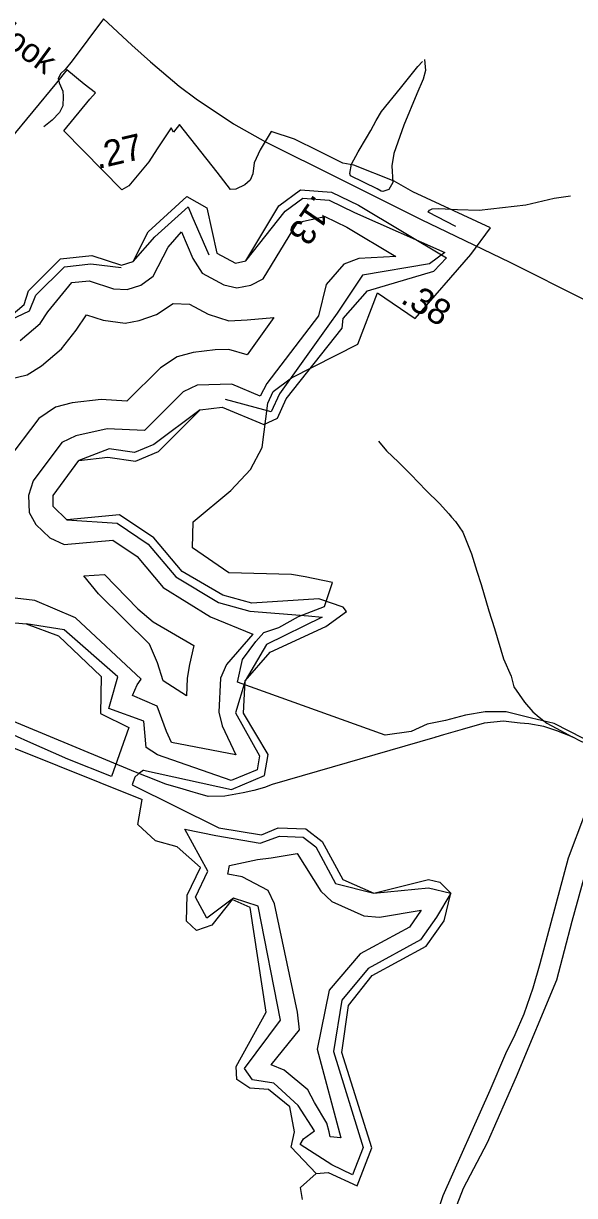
# Model space of a CAD drawing. Extents: x 945666 to 965748, y 644452 to 663300.
# Drawn here: x 953003 to 953350, y 658594 to 659330 of the extents above; entities that cross this region are included whole.
import ezdxf

# ---------------------------------------------------------------- set-up
doc = ezdxf.new("R2010")
doc.units = 0
for name, color, linetype in [('Exist Boundary Political City Limit New', 7, 'Continuous'), ('Exist Hydrographic Buffer Line', 7, 'Continuous'), ('Exist Hydrographic Creek Single Shore', 7, 'Continuous'), ('Exist Hydrographic Lake Shore', 7, 'Continuous'), ('Exist Hydrographic Pond Under 1500 Sq Ft', 7, 'Continuous'), ('Exist Railroad Siding', 7, 'Continuous'), ('Exist Road Primary NC Attributed', 7, 'Continuous'), ('Exist Road Primary US UnDivided 4 Lane Attributed', 7, 'Continuous'), ('Exist Road Secondary Mileage Tenths English Label', 7, 'Continuous'), ('Exist Road Secondary Type 51 Attributed', 7, 'Continuous'), ('Exist Road Secondary Type 51 Label', 7, 'Continuous'), ('Old_Level_49', 7, 'Continuous'), ('Sheet Sticker Preliminary CELL', 7, 'Continuous')]:
    doc.layers.add(name, color=color, linetype=linetype)

msp = doc.modelspace()

# ---------------------------------------------------------------- linework, layer by layer
at = {"layer": 'Exist Boundary Political City Limit New'}
for points in [[(953391.97, 658862.05), (953336.71, 658890.38), (953322.36, 658893.75), (953306.48, 658897.68), (953293.45, 658897.58), (953280.94, 658895.62), (953268.5, 658892.15), (953256.83, 658890), (953246.89, 658885.28), (953230.63, 658882.93), (953137.81, 658916.3), (953140.96, 658930.48), (953149.35, 658941.85), (953154.39, 658947.41), (953163.86, 658950.52), (953176.09, 658957.57), (953192.43, 658963.75), (953197.45, 658978.78), (953180.29, 658982.42), (953171.79, 658983.77), (953132.34, 658984.79), (953109.47, 659000.53), (953109.92, 659016.99), (953133.54, 659036.66), (953146, 659049.73), (953153.2, 659063.49), (953156.84, 659091.4), (953160.28, 659098.69), (953171.75, 659107.3), (953213.43, 659128.48), (953225.74, 659160.62), (953249.3, 659144.59), (953284.37, 659184.62), (953296.8, 659201.46), (953247.94, 659224.06), (953236.3, 659230.59), (953210.83, 659240.69), (953204.06, 659242.04), (953188.82, 659249.51), (953173.59, 659256.98), (953158.89, 659261.89), (953151.99, 659250.3), (953148.25, 659242.25), (953147.44, 659235.3), (953145.72, 659231.39), (953142.33, 659228.42), (953136.72, 659225.72), (953133.43, 659225.4), (953125.03, 659236.39), (953101.47, 659266.3), (953097.55, 659261.43), (953096.22, 659264.26), (953087.41, 659250.94), (953082.01, 659242.77), (953069.65, 659227.85), (953065.06, 659225.24), (953028.79, 659262.3), (953045.11, 659282.14), (953048.53, 659286.17), (953041.52, 659291.64), (953030.66, 659300.52), (953024.08, 659292.44), (952994.44, 659256.47)], [(953272.81, 658580.93), (953279.76, 658598.69), (953294.77, 658627.39), (953312.94, 658668.7), (953338.33, 658729.54), (953347.95, 658766.22), (953358.52, 658804.17)]]:
    msp.add_lwpolyline(points, dxfattribs=at)
at = {"layer": 'Exist Hydrographic Buffer Line'}
for p, q in [((953199.34, 658790.02), (953223.42, 658783.94)), ((953150.86, 658775.64), (953135.24, 658780.64))]:
    msp.add_line(p, q, dxfattribs=at)
for points in [[(953143.13, 659180.63), (953167.68, 659211.76), (953178.8, 659220.01), (953195.38, 659218.69), (953211.29, 659211), (953268.08, 659185.82), (953258.33, 659178.88), (953216.4, 659171.73), (953200.31, 659147.82), (953195.53, 659141.12), (953164.28, 659097.26), (953159.02, 659085.94), (953154.37, 659087.19), (953130.26, 659093.64)], [(953072.3, 659180.25), (953085.82, 659195.7), (953106.78, 659214.63), (953109.2, 659209.02), (953119.81, 659184.39)], [(953001.27, 659130.67), (953013.94, 659141.36), (953018.77, 659148.61), (953033.79, 659167.08), (953044.61, 659168.23), (953059.95, 659163.1), (953068.56, 659162.72), (953077.04, 659165.4), (953084.84, 659171), (953094.24, 659189.31), (953102.67, 659198.8), (953109.66, 659182.14), (953115.63, 659172.98), (953129.13, 659165.54), (953137.48, 659163.72), (953146.25, 659165.35), (953153.89, 659169.34), (953175.55, 659204.65), (953192.61, 659208.49), (953206.37, 659201.84), (953237.33, 659183.43)], [(953214.08, 659182.24), (953204.64, 659178.66), (953193.48, 659165.82), (953188.73, 659146.15), (953156.14, 659103.73), (953152.05, 659095.81), (953134.26, 659103.23), (953112.48, 659102.56), (953103.69, 659098.38), (953079.36, 659074.23), (953055.99, 659075.18), (953036.36, 659070.93), (953027.38, 659066.73), (953009.45, 659042.61), (953006.45, 659033.46), (953006.86, 659022.78), (953011.24, 659015.17), (953019.9, 659006.9), (953028.93, 659002.68), (953059.56, 659005.29), (953074.74, 658995.11), (953091.06, 658975.65), (953120.76, 658957.36), (953147.5, 658946.41)], [(953237.33, 659183.43), (953214.08, 659182.24)], [(952990.73, 659141.56), (953007.24, 659149.31), (953011.18, 659159.17), (953029.05, 659177.02), (953045.75, 659178.8), (953064.71, 659176.5)], [(952993.5, 659106.29), (953005.78, 659109.25), (953014.68, 659114.79), (953027.35, 659125.48), (953036.47, 659137.09), (953042.98, 659146.86), (953053.36, 659143.39), (953067.17, 659141.58), (953075.97, 659143.23), (953086.86, 659146.91), (953097.39, 659153.9), (953107.66, 659153.48), (953119.28, 659147.24), (953132.45, 659143.12), (953143.79, 659143.64), (953160.64, 659145.18), (953143.9, 659121.73), (953132.32, 659124.99), (953123.7, 659124.92), (953109.88, 659123.17), (953099.89, 659120.42), (953089.36, 659113.44), (953068.3, 659092.53), (953052.27, 659093.67), (953034, 659091.58), (953023.57, 659088.77), (953013.04, 659081.79), (952992.66, 659054.87)], [(953114.44, 659087.09), (953085.25, 659065.43), (953073.05, 659060.31), (953057.16, 659062.67), (953038.13, 659055.44)], [(953030.67, 659018.17), (953062.26, 659015.99), (953081.76, 659002.92), (953099.03, 658982.33), (953125.97, 658966.35), (953145.47, 658960.93), (953182.39, 658957.88), (953190.97, 658957.17), (953156.08, 658939.84), (953142.55, 658917.09), (953136.45, 658897.05), (953151.63, 658869.95), (953150.16, 658861.35), (953133.84, 658854.49), (953087.63, 658870.62), (953080.38, 658875.35), (953079.07, 658891.82), (953056.92, 658899.84), (953058.14, 658904.17), (953062.54, 658919.71), (953028.95, 658949.13), (953005.08, 658952.9)], [(953105.72, 658907.64), (953091.08, 658917.05), (953087.5, 658928.48), (953082.45, 658940.06), (953050.42, 658971.73), (953041.21, 658983.01), (953054.16, 658983.89), (953075.14, 658962.3), (953084.76, 658954.2), (953110.33, 658939.38), (953107.66, 658927.37), (953106.21, 658918.71), (953105.72, 658907.64)], [(953147.5, 658946.41), (953130.79, 658927.34), (953127.05, 658918.84), (953126.07, 658897.51), (953128.26, 658888.82), (953136.85, 658870.75), (953096.38, 658878.51), (953093.21, 658885.26), (953087.29, 658901.18), (953071.82, 658907.84), (953074.72, 658914.53), (953077.32, 658918.06), (953036.11, 658956.66), (953010.51, 658967.51), (952994.61, 658969.37)], [(953104.72, 658824.04), (953124.24, 658820.08), (953152.01, 658815.32), (953164.24, 658819.59), (953178.96, 658819.1), (953187.03, 658812.89), (953199.34, 658790.02)], [(953135.24, 658780.64), (953118.56, 658768.18), (953111.41, 658781.39), (953119.17, 658797.73), (953104.72, 658824.04)], [(953253.22, 658773.1), (953245.73, 658762.52), (953214.9, 658745.77), (953195.29, 658723.08), (953187.88, 658685.98), (953202.7, 658630.32), (953195.97, 658630.86), (953195.29, 658634.08), (953193.88, 658639.54), (953186.06, 658652.5), (953182.01, 658660.47), (953167.07, 658672.73), (953159, 658676.11), (953176.64, 658698.14), (953175.57, 658709.12), (953161.13, 658777.2), (953157, 658785.61), (953140.66, 658794.08), (953131.82, 658795.78), (953132.76, 658801.2), (953150.29, 658805.07), (953158.92, 658806.08), (953175.27, 658808.83), (953190.19, 658785.09), (953196.98, 658778.52), (953217.18, 658769.66), (953227.09, 658768.79), (953253.22, 658773.1)], [(953223.42, 658783.94), (953257.86, 658787.1), (953271.77, 658783.87), (953262.87, 658768.74), (953252.81, 658754.54), (953219.86, 658736.64), (953203.42, 658716.62), (953198.18, 658684.53), (953216.74, 658624.26), (953210.08, 658607.17), (953197.01, 658613.34), (953177.09, 658626.06), (953179.28, 658629.73), (953186.23, 658634.73), (953175.84, 658650.65), (953160.53, 658664.65), (953147.26, 658666.62), (953142.23, 658673.88), (953164.8, 658704.11), (953150.86, 658775.64)]]:
    msp.add_lwpolyline(points, dxfattribs=at)
at = {"layer": 'Exist Hydrographic Creek Single Shore'}
msp.add_lwpolyline([(953178.6, 658591.53), (953177.37, 658599.15), (953187.31, 658607.95)], dxfattribs=at)
at = {"layer": 'Exist Hydrographic Lake Shore'}
msp.add_line((953213.76, 659215.58), (953269.15, 659182.65), dxfattribs=at)
for points in [[(952991.22, 659142.59), (953003.89, 659153.28), (953006.61, 659161.94), (953026.67, 659181.99), (953046.32, 659184.09), (953064.9, 659177.88), (953072.3, 659180.25), (953081.61, 659198.9), (953106.05, 659220.97), (953118.53, 659214.05), (953124.88, 659185.52), (953136.51, 659179.27), (953143.13, 659180.63), (953163.75, 659215.31), (953177.27, 659225.34), (953196.77, 659223.8), (953213.76, 659215.58)], [(953078.66, 658861.15), (953134.01, 658848.93), (953154.79, 658857.67), (953157.08, 658870.97), (953141.64, 658896.82), (953142.55, 658917.09), (953158.26, 658935.12), (953193.21, 658951.26), (953206.17, 658960.64), (953204.13, 658963.29), (953188.94, 658968.52), (953146.82, 658965.95), (953128.57, 658970.85), (953103.01, 658985.66), (953085.27, 659006.83), (953063.61, 659021.34), (953030.67, 659018.17), (953022.01, 659026.45), (953022.03, 659033.41), (953038.13, 659055.44), (953056.4, 659057.53), (953073.72, 659054.96), (953088.19, 659061.03), (953114.44, 659087.09), (953128.26, 659088.84), (953154.24, 659078), (953162.96, 659082.04), (953168.35, 659094.03), (953203.62, 659138.42), (953204.23, 659144.4), (953219.39, 659161.78), (953261.14, 659174.29), (953269.15, 659182.65)], [(952860.77, 658934.82), (952880.31, 658954.21), (952891.76, 658959.92), (952911.26, 658958.37), (952925.64, 658974.74), (952934.45, 658977.1), (952954.78, 658960.93), (952962.01, 658945.69), (952962.4, 658935.71), (952970.97, 658929.12), (952993.38, 658953.83), (953005.08, 658952.9), (953025.37, 658945.36), (953052.15, 658919.93), (953051.66, 658896.65), (953069.49, 658887.78), (953058.67, 658857.09)], [(953058.67, 658857.09), (953031.16, 658868.01), (953006.17, 658878.95), (952973.41, 658893.74), (952951.46, 658901.19), (952937.25, 658907.3), (952931.6, 658911.47), (952918.43, 658913.07), (952884.26, 658915.8), (952852.6, 658918.55), (952821.15, 658919.89), (952792.81, 658922.06), (952751.81, 658924.83)], [(952850.65, 658901.2), (952858.46, 658907.57), (952904.88, 658906.83), (952944.73, 658896.08), (953077.86, 658842.63)], [(953078.66, 658861.15), (953075.49, 658858.53), (953073.36, 658856.64), (953071.72, 658851.91)], [(953071.72, 658851.91), (953126.03, 658824.96), (953152.87, 658820.45), (953163.27, 658824.83), (953180.79, 658824.24), (953191.08, 658816.34), (953203.92, 658792.48), (953223.42, 658783.94), (953257.82, 658792.44), (953264.83, 658790.81), (953271.77, 658783.87)], [(953187.31, 658607.95), (953171.41, 658624.47), (953173.55, 658634.11), (953170.72, 658649.72), (953157.26, 658660.62), (953145.55, 658661.55), (953137.3, 658666.82), (953136.99, 658675.12), (953155.7, 658709.12), (953145.72, 658774.87), (953134.42, 658779.79), (953121.7, 658763.77), (953112.08, 658760.41), (953105.76, 658766.33), (953106.25, 658782.63), (953114.48, 658799.96), (953099.82, 658812.85), (953086.35, 658816.75), (953075.12, 658827), (953077.86, 658842.63)], [(953187.31, 658607.95), (953194.79, 658608.64), (953212.89, 658600.1), (953222.25, 658624.07), (953203.32, 658683.8), (953207.49, 658713.38), (953222.34, 658732.08), (953256.35, 658750.55), (953267.7, 658766.56), (953271.77, 658783.87)]]:
    msp.add_lwpolyline(points, dxfattribs=at)
at = {"layer": 'Exist Hydrographic Pond Under 1500 Sq Ft'}
for points in [[(953255.15, 659307.11), (953255.78, 659300.15), (953254.4, 659294.76), (953250.45, 659285.53), (953242.35, 659265.74), (953235.92, 659248.1), (953234.78, 659240.38), (953235.36, 659229.82), (953232.76, 659225.37), (953229.08, 659224.11), (953228.04, 659224.48), (953225.6, 659225.93)], [(953225.6, 659225.93), (953208.71, 659233.96), (953208.32, 659235.56), (953209.39, 659241.41), (953213.5, 659249.2), (953218.76, 659257.86), (953221.61, 659262.55), (953224.92, 659268.82), (953228.26, 659274.42), (953240.1, 659288.97), (953251.03, 659302.72), (953253.98, 659305.84)], [(953275.01, 659202.14), (953257.65, 659211.18), (953258.45, 659212.5), (953260.1, 659213.38), (953264.18, 659213.47), (953275.95, 659212.82), (953289.54, 659212.46), (953318.8, 659215.77), (953336.77, 659220.02), (953346.91, 659221.47)]]:
    msp.add_lwpolyline(points, dxfattribs=at)
at = {"layer": 'Exist Railroad Siding'}
for points in [[(953226.29, 659067.55), (953231.33, 659061.52), (953238.99, 659054.34), (953246.7, 659046.69), (953256.34, 659036.49), (953264.66, 659028.37), (953270.58, 659021.88), (953272.23, 659019.75), (953274.69, 659017), (953279.35, 659010.41), (953284.78, 658996.77), (953288.16, 658986), (953290.79, 658977.53), (953295.64, 658961.11), (953299.12, 658950.04), (953304.79, 658930.85), (953309.7, 658919.97), (953311.35, 658913.3), (953318.14, 658903.66), (953323.36, 658897.73), (953327.21, 658894.33), (953332.14, 658890.61), (953337.96, 658887.44), (953347.97, 658882.06)], [(953347.97, 658882.06), (953338.45, 658885.72), (953330.19, 658888.51), (953320.8, 658890.03), (953315.29, 658890.58), (953309.8, 658891.26), (953304.79, 658891.7), (953292.64, 658890.51), (953278.95, 658886.62), (953267.21, 658883.17), (953262.42, 658881.7), (953262.12, 658881.72), (953261.71, 658881.6), (953159.49, 658852.02), (953154.8, 658850.25), (953148.16, 658848.26), (953141.42, 658846.77), (953129.87, 658844.69), (953119.44, 658844.54), (953112.98, 658846.49), (953109.99, 658847.29), (953103.74, 658849.08), (953092.76, 658852.36), (953080.54, 658857.02), (953073.65, 658859.74), (952964.19, 658905.2)], [(953496.77, 658849.77), (953485.79, 658839.64), (953478.4, 658834.39), (953471.81, 658830.77), (953460.56, 658827.32), (953449.44, 658826.17), (953441.49, 658826.12), (953430.21, 658828.12), (953423.52, 658830.42), (953418.54, 658832.57), (953407.73, 658840.07), (953388.26, 658855.07), (953374.86, 658865.19), (953364.57, 658872.69), (953358.9, 658876.71), (953353.63, 658879), (953347.97, 658882.06)]]:
    msp.add_lwpolyline(points, dxfattribs=at)
at = {"layer": 'Exist Road Primary NC Attributed'}
msp.add_lwpolyline([(953053.63, 659332.58), (953071.49, 659316.01), (953083.1, 659305.53), (953101.11, 659290.38), (953111.77, 659282.31), (953135.33, 659266.77), (953155.37, 659255.42), (953202.07, 659232.09), (953236.02, 659215.21), (953253.2, 659206.53), (953269.3, 659198.82), (953308.95, 659179.81), (953356.31, 659156.07), (953407.63, 659128.93), (953446.02, 659108.53), (953464.07, 659099.3), (953475.58, 659093.45), (953481.88, 659090.88), (953498.47, 659085.2)], dxfattribs=at)
at = {"layer": 'Exist Road Primary US UnDivided 4 Lane Attributed'}
msp.add_lwpolyline([(953257.84, 658557.66), (953260.82, 658574.81), (953264.56, 658586.6), (953267.02, 658594.06), (953296.49, 658660.23), (953306.25, 658683.27), (953312.16, 658695.11), (953317.78, 658708.11), (953323.45, 658724.35), (953327.83, 658739.61), (953334.9, 658765.48), (953345.72, 658806.06), (953355.87, 658833.24), (953359.65, 658840.96), (953367.9, 658854.73), (953374.86, 658865.19)], dxfattribs=at)
at = {"layer": 'Exist Road Secondary Type 51 Attributed'}
msp.add_lwpolyline([(953053.63, 659332.58), (953033.9, 659306.14), (953029.53, 659300.72), (953026.83, 659298.16), (953025.18, 659295.19), (953025.8, 659292.41), (953028.04, 659287.1), (953028.27, 659283.91), (953028.09, 659277.98), (953026.04, 659273.87), (953021.44, 659268.97), (953016.06, 659264.82)], dxfattribs=at)

# ---------------------------------------------------------------- texts
at = {"layer": 'Exist Road Secondary Mileage Tenths English Label'}
msp.add_text('.13', height=16.238, rotation=235.50017, dxfattribs=at).set_placement((953186.06, 659223.06))
at = {"layer": 'Exist Road Secondary Type 51 Label'}
msp.add_text('Overlook', height=15, rotation=323.59084, dxfattribs=at).set_placement((952952.35, 659344.86))
at = {"layer": 'Old_Level_49'}
for s, rotation, p in [('.27', 13.11831, (953050.02, 659238.22)), ('.38', 328.39341, (953239.58, 659154.81))]:
    msp.add_text(s, height=16.238, rotation=rotation, dxfattribs=at).set_placement(p)
at = {"layer": 'Sheet Sticker Preliminary CELL'}
msp.add_text('.05', height=1.9485706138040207e-12, rotation=81.53031, dxfattribs=at).set_placement((953149.3, 659163.39))
msp.add_text('.05', height=1.9485706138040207e-12, rotation=81.53031, dxfattribs=at).set_placement((953149.3, 659163.39))
msp.add_text('.05', height=1.9485706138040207e-12, rotation=81.53031, dxfattribs=at).set_placement((953149.3, 659163.39))

doc.saveas('drawing.dxf')
